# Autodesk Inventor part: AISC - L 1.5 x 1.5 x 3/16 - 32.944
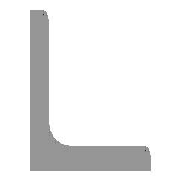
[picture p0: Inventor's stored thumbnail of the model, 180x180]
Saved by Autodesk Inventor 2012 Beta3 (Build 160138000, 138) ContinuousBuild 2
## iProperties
Created: 2010-11
Part Number: AISC - L 1.5 x 1.5 x 3/16 - 32.944
Material: Steel, Mild
Description: Angle Steel
Document SubType Name: Modeling
Standard: ANSI
Designer: Beta-8540w
Standards Organization: ANSI
Language: en-US
Size Designation: L 1.5 x 1.5 x 3/16
Categories: <MemberInstance><Categories><Category DisplayName="Structural Shapes" InternalName="089c4875-fa83-4c05-b084-43b9cc11f5ed" Mnemonic="GRDR"><CategoryParameter Dis
Stock Number: L 1.5 x 1.5 x 3/16
Density: 7.86 g/cm^3
_CCFamilyMember: 5
_CCFamilyDisplayName: ANSI L (Equal angles) - Angle Steel
_FrameMemberDoc: Frame Member File
_Version: 15.0.0
_GetPNFromCC: 1
IsCustomPart: 1
G_L: 32.944 in
G_W: 1.500 in
G_H: 1.500 in
Author: Beta-8540w
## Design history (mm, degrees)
node "Start plane"
node "End plane"
sketch "Sketch"
  geometry: L1 (38.1, 0)-(0, 0); L2 (0, 0)-(0, 38.1); L3 (0, 38.1)-(2.476, 38.1); L4 (4.762, 35.814)-(4.762, 9.589); L5 (9.588, 4.763)-(35.814, 4.763); L6 (38.1, 2.477)-(38.1, 0); L7 (0, -11.041)-(0, 31.538); L8 (-11.041, 0)-(31.538, 0); L9 (0, 48.496)-(0, -20.964) reference; L10 (-20.964, 0)-(48.496, 0) reference; A1 r 4.826 centre (9.588, 9.589) between (4.762, 9.589) and (9.588, 4.763); A2 r 2.286 centre (2.476, 35.814) between (4.762, 35.814) and (2.476, 38.1); A3 r 2.286 centre (35.814, 2.477) between (38.1, 2.477) and (35.814, 4.763); 3 further points
  constraints: 16 end point, 6 point on circle, 6 point on line, 6 tangent, 4 parallel, 3 centre point, 2 collinear, 1 equal radius, 1 horizontal, 1 perpendicular
  dimensions: "d0" = 38.1 distance between parallel lines of L6 L2 (= G_H); "d1" = 38.1 distance between parallel lines of L3 L1 (= G_H); "d2" = 4.7625 distance between parallel lines of L2 L4 (= G_T); "d3" = 4.7625 distance between parallel lines of L1 L5 (= G_T); "d10" = 0 distance between parallel lines of L7 L2 (computed from ex); "d11" = 0 distance between parallel lines of L8 L1 (computed from d10); "d14" = 4.826 radius of A1 (= G_IR); "d15" = 2.286 radius of A2 (= G_ER)
extrude "Body" new body sketch "Sketch" stored distance "d4" = 836.76542 (= G_L); taper "d5" = 0 deg
node "Driven Length"
  sketch "Sketch3"
    geometry: L1 (0, 0)-(10, 0) reference
    constraints: 2 end point, 1 horizontal
  workplane "Work Plane3"
  sketch "Sketch4"
    geometry: L1 (-2, 0)-(12, 0) reference; L2 (-2, 836.765)-(12, 836.765) reference
    dimensions: "d17" = 836.76542 distance between parallel lines of L1 L2 (derived)
body "Solid1"
other parameters: "G_H" = 38.1 [user parameter; used in 2 equation terms], "G_T" = 4.7625 [user parameter; used in 2 equation terms], "G_ER" = 2.286 [user parameter; used in 1 equation term], "G_IR" = 4.826 [user parameter; used in 1 equation term], "G_L" = 836.76542 (= d17) [user parameter; used in 1 equation term], "ex" = 0 [user parameter; used in 1 equation term], "G_OFFSET_START" = 0 [user parameter; used in 1 equation term], "G_OFFSET_END" = 0 [user parameter; used in 1 equation term], "d12" = 0 (computed from G_OFFSET_START), "d13" = 836.76542 (= G_OFFSET_END + B_L), "B_L" = 836.76542 [user parameter; used in 1 equation term], "d16" = 90 deg, "MAS" = 0.26787 [user parameter]
